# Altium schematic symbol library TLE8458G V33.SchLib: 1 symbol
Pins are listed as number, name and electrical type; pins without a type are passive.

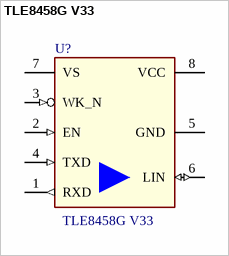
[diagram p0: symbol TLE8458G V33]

## TLE8458G V33
designator U?
LIN Transceiver with Integrated Low Drop Voltage Regulator (VCC = 3.3 V; 20 kbit/s); Manufacturer: Infineon Technologies
footprint SOIC127P600X175-8N-3
pins: 1 RXD (out) "Receive Data Output", 2 EN (in) "Enable Input", 3 WK_N (in) "Wake-up Input", 4 TXD (in) "Transmit Data Input", 5 GND (power) "Ground", 6 LIN (io) "Bus Output / Input", 7 VS (power) "Battery Supply Input", 8 VCC (power) "Output Voltage"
